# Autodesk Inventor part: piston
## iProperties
Shininess: 41.0
Length Units: 11269
Angle Units: 11279
Time Units: 11290
Mass Units: 11283
Length Display Precision: 3
Angle Display Precision: 2
Compacted: True
Created: 2003-02
Part Number: piston
Material: Acier inoxydable - 440C
Document SubType Name: Modélisation
Designer: robert
Density: 7.75 g/cm^3
Density: 0.0
Volumn: 0.0
Area: 0.0
PropertySet Name: Model Information
Control State: 0
Master: False
Checked Out: False
Author: robert
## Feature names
1. Révolution1 [Revolution]
2. Chanfrein1 [Chamfer]
3. Perçage1 [Hole]
4. Perçage2 [Hole]
5. Perçage3 [Hole]
